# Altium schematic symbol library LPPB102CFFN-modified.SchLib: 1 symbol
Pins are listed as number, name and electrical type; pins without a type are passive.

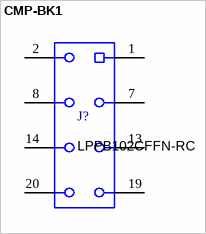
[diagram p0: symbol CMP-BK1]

## CMP-BK1
designator J?, comment LPPB102CFFN-RC
Receptacle, 1.27mm, 10x2, Gold, TH; Manufacturer: Sullins Connector Solutions; SymbolCreator: a0412235; Gender: Female; Current_A: 1A; Cert_UL: Y; Row_Count: 2; Pitch_mm: 1.27
footprint Sullins_LPPB102CFFN (Receptacle, 1.27 mm, TH)
pins: 1, 2, 7, 8, 13, 14, 19, 20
